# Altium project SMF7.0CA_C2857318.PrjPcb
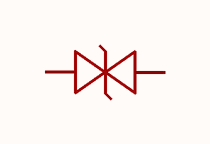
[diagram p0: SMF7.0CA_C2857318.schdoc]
1 sheet, 1 parts. Net scope: global (net labels, ports and power ports of the same name join across sheets).

## Sheet SMF7.0CA_C2857318.schdoc
size 127 x 101 mm

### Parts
D?  smf7.0ca_c2857318  [SOD-123S_L2.8-W1.8-LS3.7-BI]  (value not drawn)

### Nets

Not connected (* = marked no-connect by the designer): D? 1(C) 2(A)

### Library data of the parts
D? = smf7.0ca_c2857318: 极性:双向;反向截止电压(Vrwm):7V;钳位电压:12V;峰值脉冲电流(Ipp):16.7A;峰值脉冲功率(Ppp):200W@10/1000us;击穿电压(VBR):7.8V;; Manufacturer: JSMSEMI(杰盛微); AddInBom: yes; ModelId: 125b22121bda4d3999c0a2016797619b; ModelName: SOD-123_L2.8-W1.8-H1.4-LS3.7; ModelTransform: 145.669,70.866,0,0,0,0,0,0,0; Polarity: 双向; Reverse Stand-Off Voltage (Vrwm): 7V; Clamping Voltage: 12V; Peak Pulse Current (Ipp): 16.7A; Voltage - Breakdown: 7.8V; Reverse Leakage Current (Ir): 50uA; Number of Channels: 单路; Type: TVS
